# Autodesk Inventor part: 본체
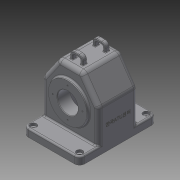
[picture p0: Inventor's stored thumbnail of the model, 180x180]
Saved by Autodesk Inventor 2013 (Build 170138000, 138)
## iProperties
Created: 2016-12
Part Number: 본체
Material: 일반
Document SubType Name: Modeling
Designer: Administrator
Density: 1 g/cm^3
Author: Administrator
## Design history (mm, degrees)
node "Front"
node "Right"
node "Top"
sketch "스케치1"
  geometry: L1 (-55, 75)-(55, 75); L2 (55, 75)-(55, -75); L3 (55, -75)-(-55, -75); L4 (-55, -75)-(-55, 75); 3 further points
  constraints: 8 end point, 2 midpoint, 2 parallel, 1 horizontal, 1 horizontal alignment, 1 perpendicular, 1 vertical alignment
  dimensions: "d3" = 110 distance of L1.start L1.end; "d5" = 150 distance of L3.end L1.start
extrude "돌출1" new body sketch "스케치1" distance "d6" = 15; taper "d7" = 0 deg
fillet "모깎기1" dims "d8" = 10
sketch "스케치2"
  geometry: L1 (45, 15)-(-45, 15) reference; L2 (-55, 0)-(-55, 15) reference; L3 (55, 15)-(55, 0) reference; L4 (-55, 15)-(-55, 80); L5 (-55, 80)-(-23.491, 125); L6 (-23.491, 125)-(23.491, 125); L7 (23.491, 125)-(55, 80); L8 (55, 80)-(55, 15); L9 (-55, 15)-(55, 15); 2 further points
  constraints: 12 end point, 2 parallel, 1 equal length, 1 horizontal, 1 midpoint, 1 perpendicular, 1 vertical alignment
  dimensions: "d9" = 65 distance of L7.end L3.start; "d10" = 110 vertical distance of L6.end L3.start; "d13" = 35 deg angle of L5 L4
extrude "돌출2" join sketch "스케치2" stored distance "d11" = 77; taper "d12" = 0 deg
sketch "스케치3"
  geometry: C1 r 37.5 at (0, 65); 1 further point
  constraints: 1 centre point, 1 vertical alignment
  dimensions: "d14" = 75 diameter of C1; "d16" = 65 distance of C1.centre point (0, 0)
extrude "돌출3" join sketch "스케치3" distance "d17" = 5; taper "d18" = 0 deg
sketch "스케치4"
  geometry: L1 (-55, 80)-(-55, 15) reference; L2 (55, 15)-(-55, 15) reference; L3 (55, 15)-(55, 80) reference; L4 (55, 80)-(23.491, 125) reference; L5 (23.491, 125)-(-23.491, 125) reference; L6 (-23.491, 125)-(-55, 80) reference; L7 (-20.888, 120)-(20.888, 120); L8 (20.888, 120)-(50, 78.424); L9 (50, 78.424)-(50, 20); L10 (50, 20)-(-50, 20); L11 (-50, 20)-(-50, 78.424); L12 (-50, 78.424)-(-20.888, 120); L13 (-45, 0)-(45, 0) reference; L14 (-50, 0)-(-50, 78.424); L15 (-20.888, 120)-(20.888, 120); L16 (50, 78.424)-(50, 0); L17 (50, 0)-(-50, 0); L18 (-50, 78.424)-(-20.888, 120); L19 (20.888, 120)-(50, 78.424); C1 r 37.5 at (0, 65) reference; 3 further points
  constraints: 24 end point, 5 collinear, 3 midpoint, 1 perpendicular, 5 other
  dimensions: "d19" = 5 distance between parallel lines of L6 L12
extrude "돌출4" cut sketch "스케치4" stored distance "d20" = 67; taper "d21" = 0 deg
sketch "스케치5"
  geometry: L1 (-59.812, 65)-(63.146, 65); L2 (-19.5, 65)-(-19.5, 92); L3 (-19.5, 92)-(-33.5, 106); L4 (-33.5, 106)-(-33.5, 65); L5 (-19.5, 65)-(-33.5, 65); L6 (-33.5, 120)-(-33.5, 78.424) reference; L7 (-43.5, 102.5)-(-43.5, 27.5) reference; 1 further point
  constraints: 10 end point, 2 collinear, 2 perpendicular, 2 point on line, 1 horizontal
  dimensions: "d22" = 65 distance from line of L1 point (0, 0); "d23" = 45 deg angle of L3 L2; "d24" = 54 diameter of L2.end L1; "d25" = 24 distance between parallel lines of L2 L7
revolve "회전1" sketch "스케치5" stored, may be unused: angle "d26" = 90 deg
sketch "스케치6"
  geometry: C1 r 37.5 at (0, -65) reference; C2 r 31 at (0, -65); 1 further point
  constraints: 1 centre point, 1 coincident
  dimensions: "d27" = 62 diameter of C2
extrude "돌출5" join sketch "스케치6" distance "d29" = 10; taper "d30" = 0 deg
sketch "스케치7"
  geometry: C1 r 37.5 at (0, 0) reference; C2 r 20 at (0, 0); 1 further point
  constraints: 1 centre point, 1 coincident
  dimensions: "d31" = 40 diameter of C2
extrude "돌출6" cut sketch "스케치7" stored distance "d33" = 10; taper "d34" = 0 deg
chamfer "모따기1" distance "d35" = 1; stored, may be unused: second distance "d36" = 2, angle "d37" = 45 deg
fillet "모깎기2" dims "d38" = 3
fillet "모깎기3" dims "d39" = 10
fillet "모깎기4" dims "d40" = 8
fillet "모깎기5" dims "d41" = 3
sketch "스케치8"
  geometry: C1 r 37.5 at (0, 0) reference; 2 further points
  constraints: 1 vertical alignment
  dimensions: "d42" = 29 distance of point (0, 29) C1.centre
hole "구멍1" sketch "스케치8" at (0, 29) diameter "d43" = 2.459; stored, may be unused: countersink angle "d47" = 90 deg, drill point angle "d49" = 118 deg; dims "d44" = 6, "d45" = 4, "d46" = 2, "d48" = 8
node "작업 평면4"
sketch "스케치9"
  geometry: L1 (-18.285, 125)-(18.285, 125) reference; L2 (-12.5, 125)-(-12.5, 132); L3 (-4.5, 140)-(4.5, 140); L4 (12.5, 132)-(12.5, 125); L5 (-12.5, 125)-(-7.5, 125); L6 (-12.5, 125)-(12.5, 125); A1 r 8 centre (-4.5, 132) between (-4.5, 140) and (-12.5, 132); A2 r 8 centre (4.5, 132) between (12.5, 132) and (4.5, 140); 4 further points
  constraints: 10 end point, 7 point on line, 4 point on circle, 4 tangent, 3 perpendicular, 2 centre point, 1 collinear, 1 equal radius, 1 midpoint, 1 vertical alignment
  dimensions: "d54" = 25 distance of point (-12.5, 140) point (12.5, 140); "d57" = 140 distance of point (0, 0) point (0, 140); "d62" = 8 radius of A1
extrude "돌출8" join sketch "스케치9" distance "d63" = 8; taper "d64" = 0 deg
sketch "스케치10"
  geometry: L1 (4.5, 140)-(-4.5, 140) reference; L2 (12.5, 125)-(-12.5, 125) reference; L3 (-4.5, 135)-(4.5, 135); L4 (7.5, 132)-(7.5, 125); L5 (7.5, 130)-(-7.5, 130); L6 (-7.5, 125)-(-7.5, 132); L7 (-7.5, 125)-(7.5, 125); A1 r 8 centre (4.5, 132) between (12.5, 132) and (4.5, 140) reference; A2 r 8 centre (-4.5, 132) between (-4.5, 140) and (-12.5, 132) reference; A3 r 3 centre (4.5, 132) between (7.5, 132) and (4.5, 135); A4 r 3 centre (-4.5, 132) between (-4.5, 135) and (-7.5, 132); 1 further point
  constraints: 10 end point, 4 point on circle, 4 point on line, 2 centre point, 2 tangent, 1 equal radius, 1 perpendicular, 1 vertical, 1 other
  dimensions: "d65" = 5 distance between parallel lines of L1 L3
extrude "돌출9" cut sketch "스케치10" distance "d66" = 8; taper "d67" = 0 deg
fillet "모깎기7" dims "d68" = 1
sketch "스케치11"
  geometry: A1 r 7 centre (-45, -65) between (-52, -65) and (-45, -72) reference; A2 r 7 centre (45, -65) between (45, -72) and (52, -65) reference; 3 further points
  constraints: 2 coincident
hole "구멍2" sketch "스케치11" at (-45, -65), (45, -65) diameter "d69" = 5; stored, may be unused: countersink angle "d73" = 90 deg, drill point angle "d75" = 118 deg; dims "d70" = 6, "d71" = 12, "d72" = 5, "d74" = 15
sketch "스케치12"
  geometry: C1 r 20 at (0, 0) reference; 2 further points
  constraints: 1 vertical alignment
  dimensions: "d76" = 26 distance of point (0, -26) C1.centre
hole "구멍3" sketch "스케치12" at (0, -26) diameter "d77" = 2.459; stored, may be unused: countersink angle "d81" = 90 deg, drill point angle "d83" = 118 deg; dims "d78" = 6, "d79" = 12, "d80" = 5, "d82" = 8
chamfer "모따기2" distance "d87" = 1; stored, may be unused: second distance "d88" = 2, angle "d89" = 45 deg
sketch "스케치13"
  geometry: L1 (0, 130)-(0, 0) reference; L2 (-51.833, 38.769)-(-38.167, 91.231); L3 (-76.847, 26.5)-(-18, 26.5) reference; 4 further points
  constraints: 2 end point, 1 midpoint, 1 other
  dimensions: "d90" = 45 distance from line of point (-45, 65) L1; "d91" = 38.5 distance from line of point (-45, 65) L3
extrude "돌출10" join sketch "스케치13" distance "d92" = 0.5; taper "d93" = 0 deg
node "본체"
pattern_circular "원형 패턴1" dims angle "d51" = 360 deg
mirror "대칭2"
mirror "대칭3"
pattern_circular "원형 패턴2" dims angle "d85" = 360 deg
node "투영된 루프1"
other parameters: "d0" = 0, "d1" = 0, "d2" = 0, "d53" = 26
